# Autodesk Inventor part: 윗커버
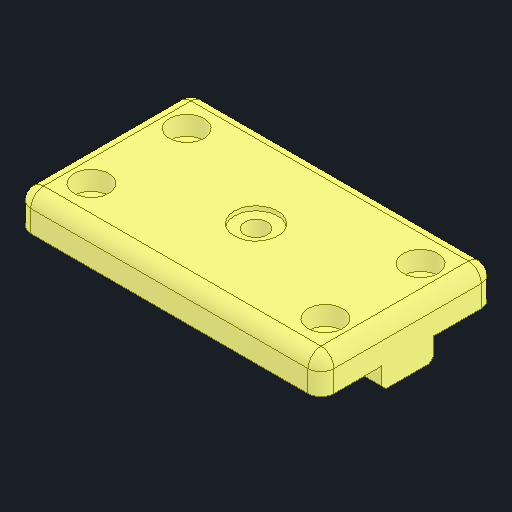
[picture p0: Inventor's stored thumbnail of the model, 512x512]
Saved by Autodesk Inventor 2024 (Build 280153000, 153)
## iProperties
Created: 2025-02
Part Number: 윗커버
Material: 강철, 주조
Document SubType Name: Modeling
Designer: kh_501
Density: 7.85 g/cm^3
Appearance: 기본값
Author: jhkim
Sending System: Autodesk Inventor 2025
Preprocessor: ST-DEVELOPER v20
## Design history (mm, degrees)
node "윗커버1"
node "솔리드2"
node "솔리드1"
